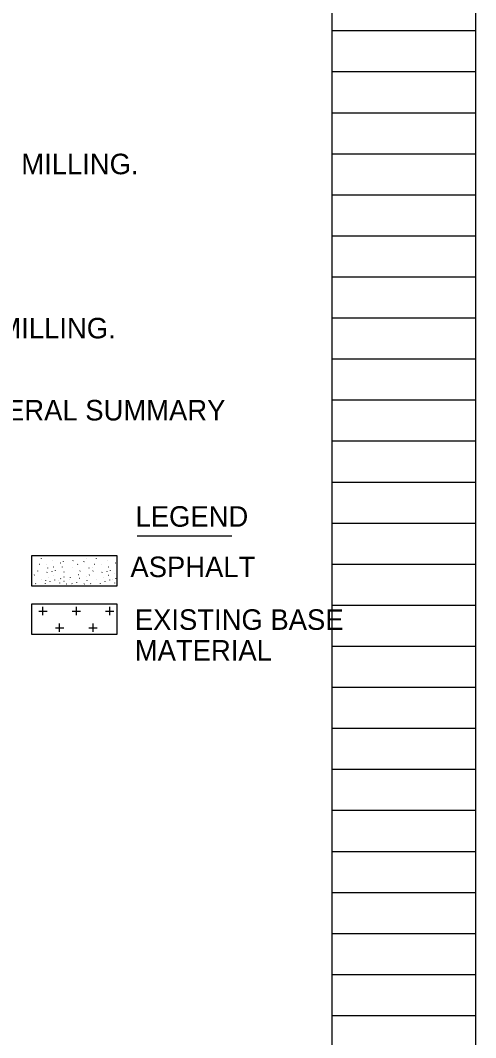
# Model space of a CAD drawing. Extents: x -28.8 to 41.7, y 0 to 25.4.
# Drawn here: x 14.13 to 17.24, y 5.87 to 12.81 of the extents above; entities that cross this region are included whole.
import ezdxf

# ---------------------------------------------------------------- set-up
doc = ezdxf.new("R2010")
doc.units = 0
for name, color, linetype in [('Default', 7, 'Continuous'), ('SH_Data', 7, 'Continuous'), ('TX_P_Misc', 7, 'Continuous')]:
    doc.layers.add(name, color=color, linetype=linetype)

msp = doc.modelspace()

# ---------------------------------------------------------------- linework, layer by layer
at = {"layer": 'Default'}
for p, q in [((14.9285, 9.2934), (15.5747, 9.2934)), ((14.2614, 9.0964), (14.2604, 9.0972)), ((14.2745, 9.1367), (14.275, 9.1387)), ((14.311, 9.0987), (14.3115, 9.1004)), ((14.3534, 9.1237), (14.3524, 9.1246)), ((14.4072, 9.1069), (14.4052, 9.1059)), ((14.4257, 9.1186), (14.4247, 9.1197)), ((14.49, 9.1221), (14.4907, 9.1242)), ((14.524, 9.0984), (14.522, 9.0981)), ((14.5614, 9.1154), (14.5614, 9.1154)), ((14.5657, 9.1149), (14.5664, 9.1169)), ((14.5817, 9.1387), (14.5817, 9.1387)), ((14.6372, 9.0964), (14.6362, 9.0972)), ((14.6502, 9.1367), (14.651, 9.1387)), ((14.6867, 9.0987), (14.6875, 9.1004)), ((14.7294, 9.1237), (14.7284, 9.1246)), ((14.783, 9.1069), (14.781, 9.1059)), ((14.2282, 9.0257), (14.2264, 9.0252)), ((14.2509, 9.0514), (14.2514, 9.0532)), ((14.3137, 9.0439), (14.3119, 9.0434)), ((14.3185, 9.0722), (14.319, 9.0739)), ((14.3482, 9.0486), (14.349, 9.0506)), ((14.3602, 9.0784), (14.3582, 9.0779)), ((14.3712, 9.0572), (14.3717, 9.0591)), ((14.4189, 9.0794), (14.418, 9.0806)), ((14.4299, 9.0459), (14.4305, 9.0477)), ((14.4852, 9.0782), (14.4842, 9.0792)), ((14.5304, 9.0277), (14.5284, 9.0271)), ((14.5382, 9.0514), (14.539, 9.0532)), ((14.601, 9.0722), (14.6019, 9.0739)), ((14.604, 9.0257), (14.602, 9.0252)), ((14.6215, 9.0769), (14.6215, 9.0769)), ((14.6269, 9.0514), (14.6274, 9.0532)), ((14.6895, 9.0439), (14.6877, 9.0434)), ((14.724, 9.0486), (14.7249, 9.0506)), ((14.736, 9.0784), (14.734, 9.0779)), ((14.747, 9.0572), (14.7475, 9.0591)), ((14.7749, 9.0372), (14.7749, 9.0372)), ((14.2359, 8.9662), (14.2349, 8.9674)), ((14.2734, 8.9927), (14.2724, 8.9937)), ((14.3019, 8.9659), (14.3027, 8.9679)), ((14.3054, 8.9887), (14.3044, 8.9897)), ((14.32, 9.0079), (14.3205, 9.0096)), ((14.3337, 8.9796), (14.3344, 8.9816)), ((14.356, 9.0217), (14.355, 9.0229)), ((14.3657, 8.9897), (14.3662, 8.9917)), ((14.3907, 8.9867), (14.3907, 8.9867)), ((14.4012, 8.9702), (14.4002, 8.9712)), ((14.4072, 9.0004), (14.4062, 9.0016)), ((14.4297, 8.9801), (14.4285, 8.9811)), ((14.431, 9.0111), (14.429, 9.0107)), ((14.4454, 8.9624), (14.4444, 8.9634)), ((14.465, 8.9966), (14.465, 8.9966)), ((14.4737, 9.0096), (14.4742, 9.0114)), ((14.4845, 8.9662), (14.4834, 8.9674)), ((14.5177, 8.9732), (14.5167, 8.9741)), ((14.5375, 9.0012), (14.5357, 9.0007)), ((14.5644, 8.9704), (14.5644, 8.9704)), ((14.5685, 8.9644), (14.5667, 8.9634)), ((14.581, 9.0121), (14.581, 9.0121)), ((14.5882, 8.9887), (14.5872, 8.9897)), ((14.6117, 8.9662), (14.6107, 8.9674)), ((14.6492, 8.9927), (14.6482, 8.9937)), ((14.6777, 8.9659), (14.6785, 8.9679)), ((14.6959, 9.0079), (14.6965, 9.0096)), ((14.7095, 8.9796), (14.7104, 8.9816)), ((14.732, 9.0217), (14.7309, 9.0229)), ((14.7415, 8.9897), (14.742, 8.9917)), ((14.7629, 8.9957), (14.7629, 8.9957)), ((14.777, 8.9702), (14.776, 8.9712)), ((14.783, 9.0004), (14.782, 9.0016)), ((14.3847, 8.9527), (14.3855, 8.9522)), ((14.3855, 8.9522), (14.386, 8.9517)), ((14.7605, 8.9527), (14.7614, 8.9522)), ((14.7614, 8.9522), (14.7619, 8.9517)), ((14.2569, 8.7796), (14.3139, 8.7796)), ((14.2852, 8.7509), (14.2852, 8.8081)), ((14.4852, 8.7796), (14.542, 8.7796)), ((14.4852, 8.7796), (14.542, 8.7796)), ((14.5137, 8.7509), (14.5137, 8.8081)), ((14.7134, 8.7796), (14.7705, 8.7796)), ((14.742, 8.7509), (14.742, 8.8081)), ((14.3995, 8.6367), (14.3995, 8.6939)), ((14.6277, 8.6367), (14.6277, 8.6939)), ((14.3709, 8.6652), (14.428, 8.6652)), ((14.5994, 8.6652), (14.6565, 8.6652))]:
    msp.add_line(p, q, dxfattribs=at)
for points in [[(14.2102, 9.1596), (14.7904, 9.1596), (14.7904, 8.9504), (14.2102, 8.9504)], [(14.2102, 8.8289), (14.7904, 8.8289), (14.7904, 8.6196), (14.2102, 8.6196)]]:
    msp.add_lwpolyline(points, close=True, dxfattribs=at)
at = {"layer": 'SH_Data'}
for p, q in [((16.26, 0.98), (16.26, 21.14)), ((17.24, 0.98), (17.24, 21.14)), ((16.26, 12.74), (17.24, 12.74)), ((16.26, 12.46), (17.24, 12.46)), ((16.26, 12.18), (17.24, 12.18)), ((16.26, 11.9), (17.24, 11.9)), ((16.26, 11.62), (17.24, 11.62)), ((16.26, 11.34), (17.24, 11.34)), ((16.26, 11.06), (17.24, 11.06)), ((16.26, 10.78), (17.24, 10.78)), ((16.26, 10.5), (17.24, 10.5)), ((16.26, 10.22), (17.24, 10.22)), ((16.26, 9.94), (17.24, 9.94)), ((16.26, 9.66), (17.24, 9.66)), ((16.26, 9.38), (17.24, 9.38)), ((16.26, 9.1), (17.24, 9.1)), ((16.26, 8.82), (17.24, 8.82)), ((16.26, 8.54), (17.24, 8.54)), ((16.26, 8.26), (17.24, 8.26)), ((16.26, 7.98), (17.24, 7.98)), ((16.26, 7.7), (17.24, 7.7)), ((16.26, 7.42), (17.24, 7.42)), ((16.26, 7.14), (17.24, 7.14)), ((16.26, 6.86), (17.24, 6.86)), ((16.26, 6.58), (17.24, 6.58)), ((16.26, 6.3), (17.24, 6.3)), ((16.26, 6.02), (17.24, 6.02))]:
    msp.add_line(p, q, dxfattribs=at)

# ---------------------------------------------------------------- texts
at = {"layer": 'Default'}
for s, p in [('PAVEMENT REPAIRS SHALL BE DONE BEFORE MILLING.', (9.82, 11.76)), ('PAVEMENT REPAIRS SHALL BE DONE AFTER MILLING.', (9.82, 10.64)), ('LEGEND', (14.9174, 9.355)), ('ASPHALT', (14.8825, 9.0111)), ('EXISTING BASE', (14.9127, 8.6514)), ('MATERIAL', (14.9127, 8.4414))]:
    msp.add_text(s, height=0.14, dxfattribs=at).set_placement(p)
at = {"layer": 'TX_P_Misc'}
msp.add_text(' CARRIED TO GENERAL SUMMARY', height=0.14, dxfattribs=at).set_placement((12.3691, 10.08))

doc.saveas('drawing.dxf')
